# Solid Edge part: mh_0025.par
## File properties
Title: handle_f
Author: edge
Template: normal.par
Last saved by: edge
Revision: 39
Application: Solid Edge
Material: ＡＢＳ
非切断部品: False
文書内容のタイプ: 0
Density: 0.001200 g/mm^3
Accuracy: 0.99
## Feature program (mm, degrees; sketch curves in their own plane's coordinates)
sketch for "unnamed Protrusion 1" plane through (0, 0, 0) normal (0, 0, 1) x-axis (1, 0, 0)
  line (-40, 7.5) -> (40, 7.5)
  line (40, 7.5) -> (40, -7.5)
  line (40, -7.5) -> (-40, -7.5)
  line (-40, -7.5) -> (-40, 7.5)
extrude "unnamed Protrusion 1" add finite 6 along -normal
thinwall "Thinwall_1"  Thickness = 1 mm
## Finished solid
Body 1: solid body, 11 faces, 24 edges, 16 vertices.
  Faces by surface: plane 11
  Edges by curve: line 24
Bounding box of the edges (mm): 80.000 x 15.000 x 6.000, from (-40, -7.5, -6) to (40, 7.5, 0).
Planar faces by outward normal: +x 2, +y 2, +z 2, -x 2, -y 2, -z 1
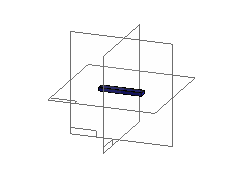
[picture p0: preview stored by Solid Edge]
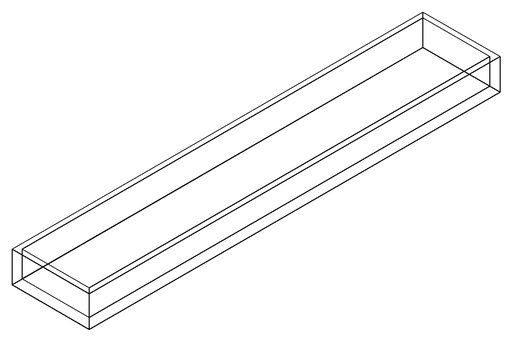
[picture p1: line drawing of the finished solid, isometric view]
